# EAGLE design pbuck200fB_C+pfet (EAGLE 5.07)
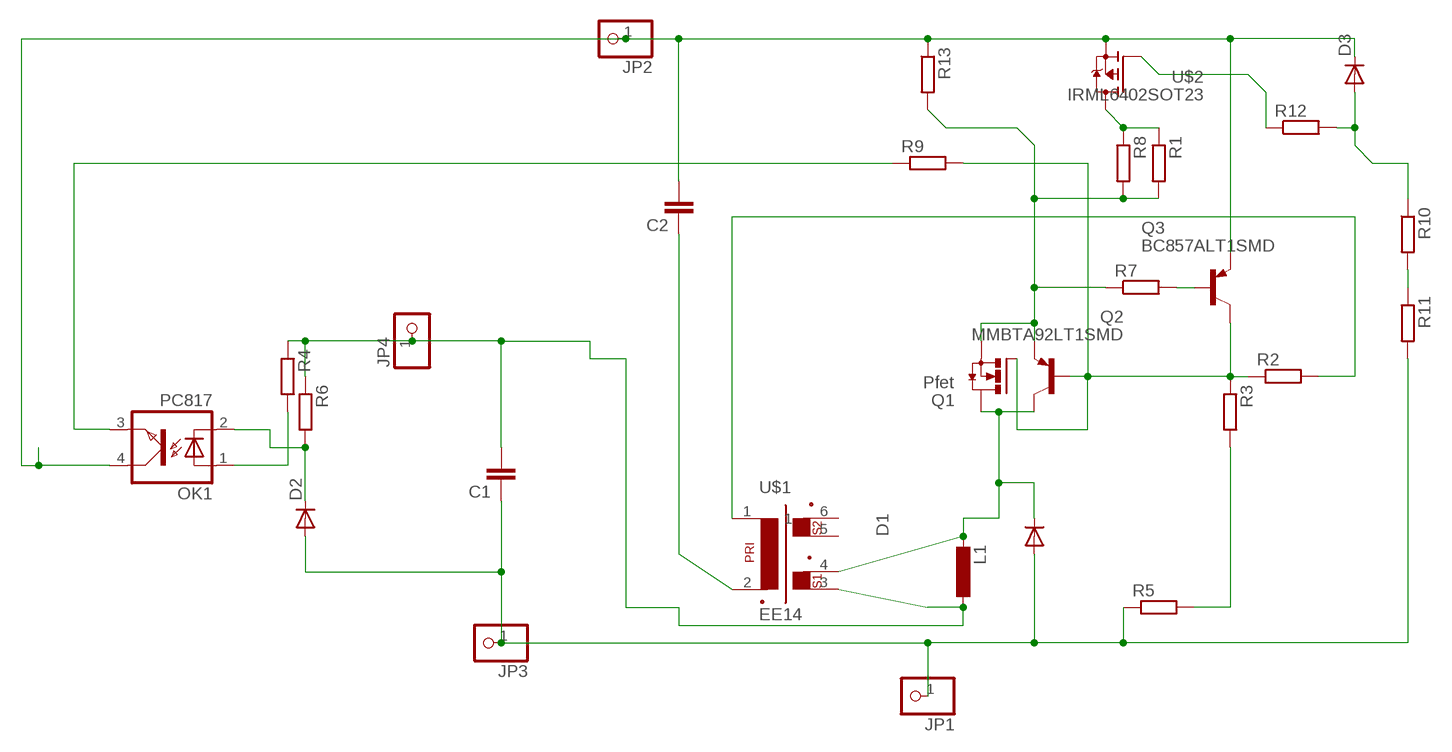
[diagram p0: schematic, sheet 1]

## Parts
C1  C-EU025-025X050  [C025-025X050]
C2  C-EUC0805  [C0805]
D1  DIODE-SMC  [SMC]
D2  DIODE-MINIMELF  [MINIMELF]
D3  DIODE-MINIMELF  [MINIMELF]
JP1  PINHD-1X11MM6  [1X1MM8]
JP2  PINHD-1X11MM6  [1X1MM8]
JP3  PINHD-1X11MM6  [1X1MM8]
JP4  PINHD-1X11MM6  [1X1MM8]
L1  L-EU0204/5  [0204/5]
OK1  PC817  [DIL04]
Q1  Pfet  N-HEXFET_DPAK-  [TO252]
Q2  MMBTA92LT1SMD  [SOT23-BEC]
Q3  BC857ALT1SMD  [SOT23-BEC]
R1  R-EU_R1206  [R1206]
R2  R-EU_R0805  [R0805]
R3  R-EU_R1206  [R1206]
R4  R-EU_R0805  [R0805]
R5  R-EU_R1206  [R1206]
R6  R-EU_R0805  [R0805]
R7  R-EU_R1206  [R1206]
R8  R-EU_R1206  [R1206]
R9  R-EU_R0805  [R0805]
R10  R-EU_R1206  [R1206]
R11  R-EU_R1206  [R1206]
R12  R-EU_R1206  [R1206]
R13  R-EU_R1206  [R1206]
U$1  EE14  [EE14]
U$2  IRML6402SOT23  [SOT23]

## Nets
-: C1.1 D1.A D2.A JP1.1 JP3.1 R5.1 R11.2
B1C2: OK1.3(EMIT) R9.1
C1: D1.C L1.2 Q1.3(D) Q2.C U$1.4
EB: Q1.2(S) Q2.E R1.2 R7.1 R8.2 R13.2
N$1: R3.2 R5.2
N$2: Q1.1(G) Q2.B Q3.C R2.1 R3.1 R9.2
N$3: Q3.B R7.2
N$4: R2.2 U$1.1
N$6: C2.1 U$1.2
N$7: D2.C OK1.2(C) R6.2
N$8: OK1.1(A) R4.2
N$9: D3.A R10.1 R12.2
N$10: R1.1 R8.1 U$2.3(D)
N$12: R10.2 R11.1
N$13: R12.1 U$2.1(G)
OUT+: C1.2 JP4.1 L1.1 R4.1 R6.1 U$1.3
VPLUS: C2.2 D3.C JP2.1 OK1.4(COL) Q3.E R13.1 U$2.2(S)
Unconnected: U$1.5 U$1.6

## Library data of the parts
C1 C2 = rcl:C-EU: CAPACITOR, European symbol
D1-D3 = diode:DIODE-: DIODE
JP1-JP4 = pinhead:PINHD-1X1: PIN HEADER
L1 = rcl:L-EU: INDUCTOR, European symbol
OK1 = optocoupler:PC817: SHARP OPTO COUPLER
Q1 = transistor-power:N-HEXFET_?-*: HEXFET® Power MOSFET
Q2 = transistor-pnp:MMBTA92*: PNP Transistror
Q3 = transistor-pnp:BC857*: PNP Transistror
R1-R13 = rcl:R-EU_: RESISTOR, European symbol
U$1 = trafo:EE14
U$2 = transistor-fet:IRML6402

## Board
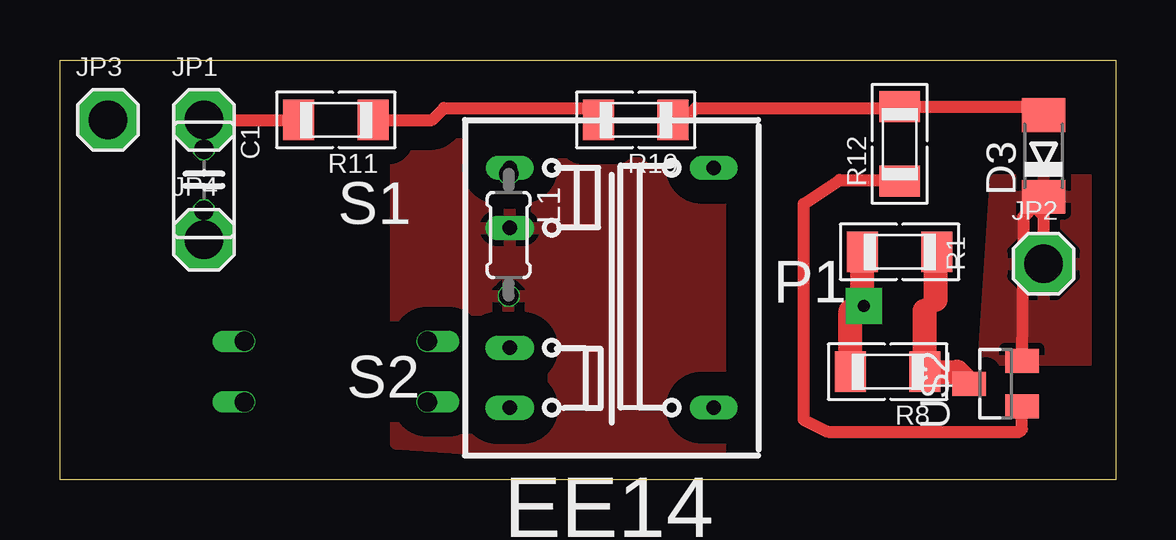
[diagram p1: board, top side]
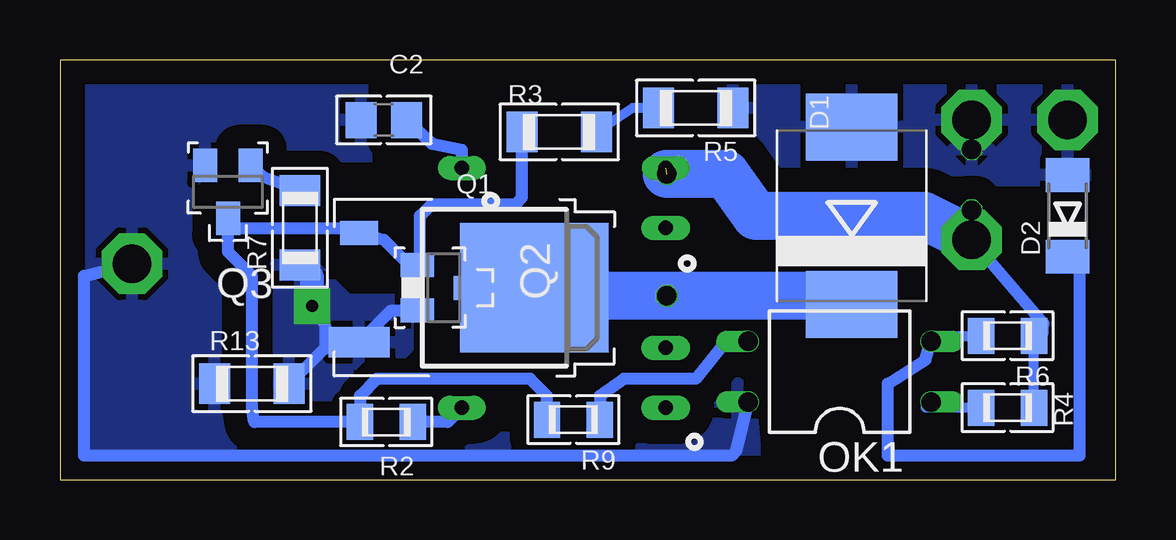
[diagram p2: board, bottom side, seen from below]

Size 44 x 17.5 mm. Coordinates in mm from the lower left corner, seen from the top.
Outline: 0,17.5 44,17.5 44,0 0,0 0,17.5
Copper layers (1*16): Top 0.035mm / dielectric 1.5mm / Bottom 0.035mm
Design rules "default": minimum track width 10mil, minimum drill 20mil, track to track 8mil, track to pad 8mil, pad to pad 8mil, via to via 8mil, smd to smd 8mil, copper to edge 40mil, drill to drill 8mil, minimum pad ring 1mil, minimum via ring 8mil, stop-mask expansion 4mil, vias tented up to drill 0mil, thermal gap 10mil

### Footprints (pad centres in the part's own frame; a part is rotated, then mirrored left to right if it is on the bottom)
C025-025X050 = drill 0.813 octagon: 1 -1.27,0; 2 1.27,0
C0805 = smd 1.3 x 1.5: 1 -0.95,0; 2 0.95,0
SMC = smd 2.8 x 3.8: A 3.7,0; C -3.7,0
MINIMELF = smd 1.4 x 1.8: A 1.7,0; C -1.7,0
1X1MM8 = drill 1.6 pad 2.54 octagon: 1 0,0
0204/5 = drill 0.813 octagon: 1 -2.54,0; 2 2.54,0
DIL04 = drill 0.813 offset: 1 -1.27,-3.81; 2 1.27,-3.81; 3 1.27,3.81; 4 -1.27,3.81
TO252 = smd 1 x 1.6: 1 -2.28,-3.53 | smd 1.27 x 2.54: 2 2.28,-3.53 | smd 5.4 x 6.2: 3 0,3.77
SOT23-BEC = smd 1 x 1.4: B -0.95,-1.1; C 0,1.1; E 0.95,-1.1
R1206 = smd 1.3 x 1.7: 1 -1.55,0; 2 1.55,0
R0805 = smd 1.1 x 1.5: 1 -1.1,0; 2 1.1,0
EE14 = drill 0.6 pad 1 long: 1 4.25,-5; 2 4.25,5; 3 -4.25,5 | drill 0.6 pad 1.016 long: 4 -4.25,2.5; 5 -4.25,-2.5; 6 -4.25,-5
SOT23 = smd 1 x 1.4: 1 -0.95,-1.1; 2 0.95,-1.1; 3 0,1.1

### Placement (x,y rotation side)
C1  6,12.5 270 top
C2  30.5,15 180 bottom
D1  11,11 90 bottom
D2  2,11 90 bottom
D3  41,13.5 90 top
JP1  6,15 0 top
JP2  41,9 0 top
JP3  2,15 0 top
JP4  6,10 0 top
L1  18.7,10.2 270 top
OK1  11.5,4.5 90 bottom
Q1  28,8 270 bottom
Q2  28,8 270 bottom
Q3  37,12 180 bottom
R1  35,9.5 180 top
R2  30.4,2.4 0 bottom
R3  23.19,14.5 0 bottom
R4  4.5,3 180 bottom
R5  17.5,15.5 180 bottom
R6  4.5,6 180 bottom
R7  34,10.5 90 bottom
R8  34.5,4.5 180 top
R9  22.6,2.5 180 bottom
R10  24,15 180 top
R11  11.5,15 180 top
R12  35,14 90 top
R13  36,4 0 bottom
U$1  23,8 0 top
U$2  39,4 90 top

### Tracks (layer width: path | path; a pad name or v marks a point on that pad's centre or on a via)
-
  Top 0.5: JP1.1 R11.2
  pour Bottom (isolate 1, rank 2): 1.5,16.5 16,16.5 16,13.5 15,12.5 1,12.5
B1C2
  Bottom 0.5: OK1.3 16.23,5.77 17.5,4.2 20.5,4.2 21.5,3.5 R9.1
C1
  Bottom 0.406: 24.14,7.66 Q1.3 25.49,7.87 26.65,7.75
  Bottom 0.5: L1.2 18.56,7.8 | D1.C 11.14,7.66 | Q2.C 25.62,8 25.49,7.87
  Bottom 2: 11.14,7.66 L1.2 24.14,7.66
  pour Top (isolate 1, rank 2): 14,16.5 27.5,16.5 27.5,1 21,1 14,1.5
EB  (via drill 0.5 pad 1.5)
  Top 0.5: 32.95,7.05 v33.5,7.25 33.45,7.05
  Top 1: R8.2 32.95,7.05 | 33.45,7.05 R1.2
  Bottom 0.5: 31.5,5.5 31,5.5 | 31.5,5.5 Q1.2 30.2,7.05 Q2.E | 32.95,5.5 31.5,5.5 | 32.95,5.5 R13.2 | 32.95,5.5 32.95,6.45 v33.5,7.25 | 33.5,8.45 R7.1
  Bottom 1: v33.5,7.25 33.5,8.45
  pour Bottom (isolate 0.61): 29.5,7.5 32,7.5 33.5,9 35,9 35,3 32,3 29.5,5.5
N$1
  Bottom 0.406: R5.2 20.13,15.5 R3.2
N$2
  Bottom 0.5: R3.1 24.74,11.76 25,11.5 28.5,11.5 29,11 29,9.05 Q2.B 29.45,8.95 30.5,10 32,10.5 | 32,10.5 Q1.1 | R9.2 23.7,3.5 24.4,4.2 30.8,4.2 31.5,3.5 R2.1 35.9,2.4 36,3 36,8.5 37,9.5 Q3.C 37.1,10.5 32,10.5
N$3
  Bottom 0.5: R7.2 35.5,12.6 Q3.B
N$4
  Bottom 0.5: R2.2 27.85,2.4 U$1.1
N$6
  Bottom 0.5: U$1.2 27.25,13.75 28.5,14 C2.1
N$7
  Bottom 0.406: R6.2 7.46,6 OK1.2
  Bottom 0.5: OK1.2 7.92,5 9.5,4 9.5,1 1.5,1 1.5,9 1.8,9.3 D2.C
N$8
  Bottom 0.406: R4.2 7.92,3 OK1.1
N$9
  Top 0.5: R10.1 26,15 26.5,15.5 34.95,15.5 R12.2 40.65,15.55 D3.A
N$10
  Top 0.5: 36.05,7.05 36.5,7.5 | 36.5,8.95 R1.1
  Top 1: 36.05,7.05 R8.1 37.4,4.5 U$2.3 | 36.5,7.5 36.5,8.95
N$12
  Top 0.5: R11.1 15.5,15 16,15.5 21.95,15.5 R10.2
N$13
  Top 0.5: U$2.1 40.1,2.1 40,2 32,2 31,2.5 31,11.5 32.5,12.5 34.95,12.5 R12.1
OUT+  (1 unrouted)
  Bottom 0.406: 3,6.5 3,6.1 R6.1 R4.1
  Bottom 0.5: C1.2 JP4.1 3,6.5
  Bottom 2: JP4.1 8,11 15,11 16.24,12.74 L1.1
VPLUS
  Top 0.5: U$2.2 40.15,10.95 40.6,11.4 | 40.6,11.4 D3.C | JP2.1 41,11 40.6,11.4
  Bottom 0.5: JP2.1 43,8.5 43,1 16,1 15.81,1.19 OK1.4
  pour Bottom (isolate 1, rank 3): 31.5,17 43.5,17 44,1 15,1 15.5,6.5 36.5,6.5 36.5,12.5 36,13.5 31,13.5 31,16.5
  pour Top (isolate 0.61): 39,12.5 43,12.5 43,5 38.5,5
